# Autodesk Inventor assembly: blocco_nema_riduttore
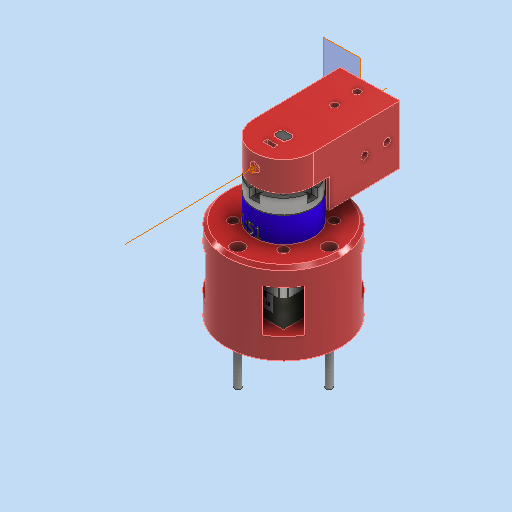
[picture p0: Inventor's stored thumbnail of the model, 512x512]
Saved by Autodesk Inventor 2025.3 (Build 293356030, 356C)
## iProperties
Created: 2026-01
Part Number: blocco_nema_riduttore
Document SubType Name: Assembly
Designer: R5800u
Author: R5800u
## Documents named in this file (6)
- C:\Users\R5800u\Desktop\antropomorfo_nema4\blocco_nema_riduttore.iam
- C:\Users\R5800u\Desktop\antropomorfo_nema4\NEMA 42SHDC3030Z.ipt
- C:\Users\R5800u\Desktop\antropomorfo_nema4\blocco_albero.ipt
- C:\Users\R5800u\Desktop\antropomorfo_nema4\blocco_nema.ipt
- C:\Users\R5800u\Desktop\antropomorfo_nema4\ANSI B18.3.1M - M4x0,7 x 50(1).ipt
- C:\Users\R5800u\Desktop\antropomorfo_nema4\riduttore_nema17_3.ipt
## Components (8 placed, 5 different names)
1. NEMA 42SHDC3030Z:1 — Angolo:3, Coincidente:15, Coincidente:16, Angolo:4
2. blocco_nema:1 — Angolo:2, Tangente:1, Allineato:1, Coincidente:10, Coincidente:12, Coincidente:14, Rotazionale:1
3. Vite forgiata a testa incassata - Metrico M4x0,7 x 50:2 — Coincidente:10
4. Vite forgiata a testa incassata - Metrico M4x0,7 x 50:1 — Coincidente:12
5. Vite forgiata a testa incassata - Metrico M4x0,7 x 50:4 — Coincidente:14
6. Vite forgiata a testa incassata - Metrico M4x0,7 x 50:3 — Rotazionale:1
7. blocco_albero:1 — Coincidente:17, Coincidente:18
8. riduttore_nema17_3:1 — Coincidente:15, Coincidente:16, Angolo:4, Coincidente:17, Coincidente:18
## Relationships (13: Mate 7, Angle 3, Tangent 1, Flush 1, RevoluteJoint 1)
- Angolo:2 [Angle]: blocco_nema:1
- Angolo:3 [Angle]: NEMA 42SHDC3030Z:1
- Tangente:1: blocco_nema:1
- Allineato:1 [Flush]: blocco_nema:1
- Coincidente:10 [Mate]: blocco_nema:1 ↔ Vite forgiata a testa incassata - Metrico M4x0,7 x 50:2
- Coincidente:12 [Mate]: blocco_nema:1 ↔ Vite forgiata a testa incassata - Metrico M4x0,7 x 50:1
- Coincidente:14 [Mate]: blocco_nema:1 ↔ Vite forgiata a testa incassata - Metrico M4x0,7 x 50:4
- Rotazionale:1 [RevoluteJoint]: blocco_nema:1 ↔ Vite forgiata a testa incassata - Metrico M4x0,7 x 50:3
- Coincidente:15 [Mate]: NEMA 42SHDC3030Z:1 ↔ riduttore_nema17_3:1
- Coincidente:16 [Mate]: NEMA 42SHDC3030Z:1 ↔ riduttore_nema17_3:1
- Angolo:4 [Angle]: NEMA 42SHDC3030Z:1 ↔ riduttore_nema17_3:1
- Coincidente:17 [Mate]: blocco_albero:1 ↔ riduttore_nema17_3:1
- Coincidente:18 [Mate]: blocco_albero:1 ↔ riduttore_nema17_3:1
